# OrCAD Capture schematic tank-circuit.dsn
size A; title: RLC Tank Circuit
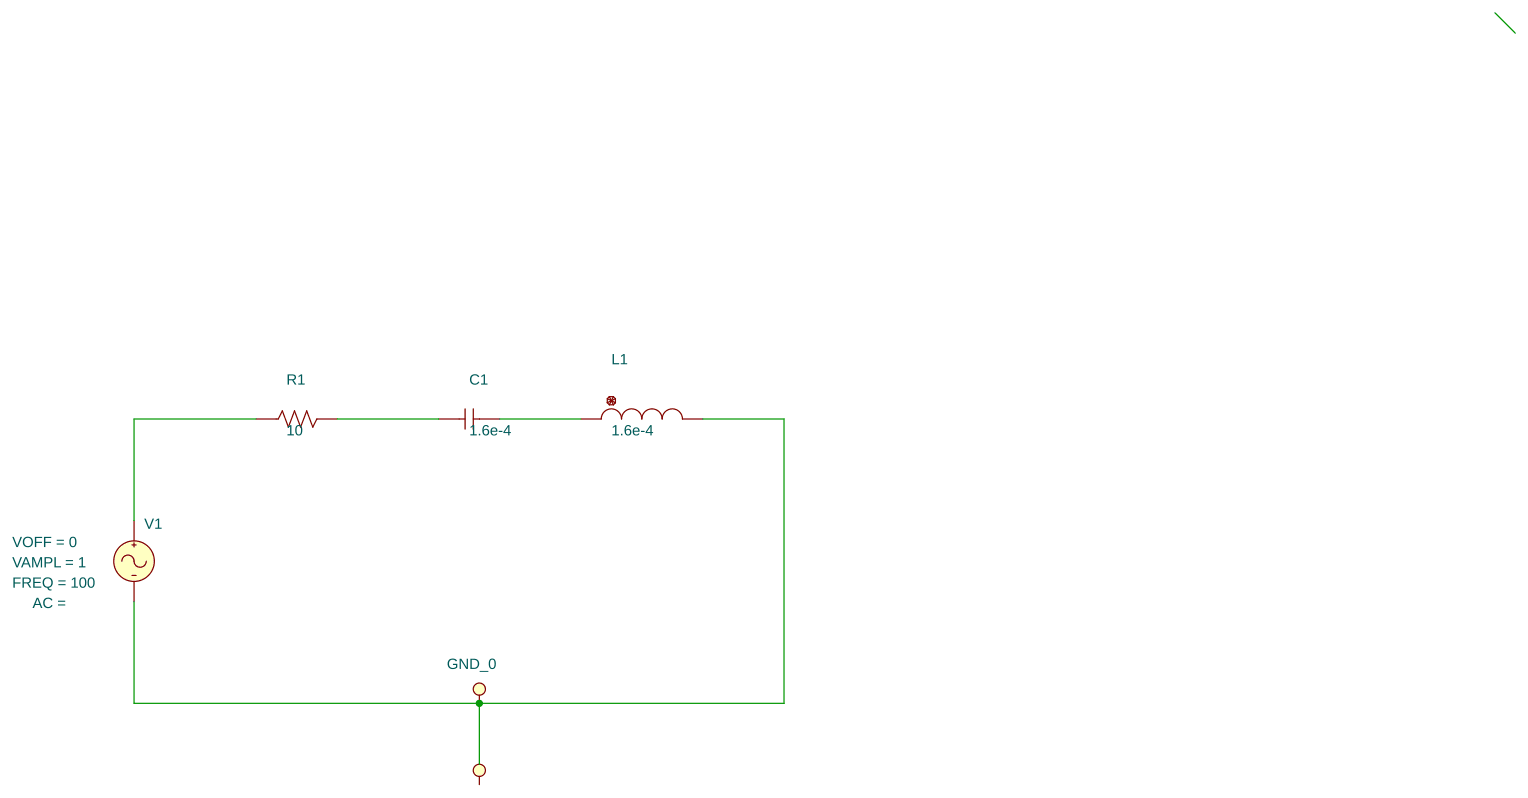
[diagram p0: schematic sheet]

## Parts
C1  1.6e-4  [cap196]
L1  1.6e-4  [DISC350x175LS200x100034]
R1  10  [AXRC05]
V1  VSIN

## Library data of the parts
C1 = C
L1 = L
R1 = R
V1 = VSIN: FREQ: 100; VAMPL: 1; VOFF: 0

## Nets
0: L1.2 V1.2(-)
N14412: R1.1 V1.1(+)
N14419: C1.1 R1.2
N14423: C1.2 L1.1
